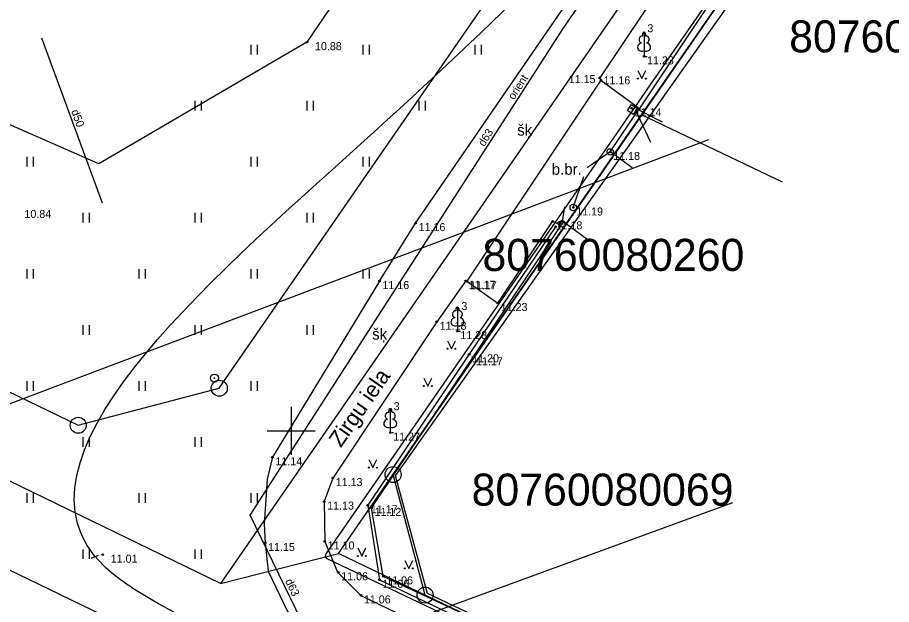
# Model space of a CAD drawing. Extents: x 503353 to 504004, y 304662 to 305049.
# Drawn here: x 503582.9 to 503637.5, y 304889.2 to 304925.8 of the extents above; entities that cross this region are included whole.
import ezdxf

# ---------------------------------------------------------------- set-up
doc = ezdxf.new("R2010")
doc.units = 0
for name, color, linetype in [('13', 7, 'Continuous'), ('24', 7, 'Continuous'), ('25', 7, 'Continuous'), ('59', 7, 'Continuous'), ('APGR_ELEM_####_####_#', 7, 'Continuous'), ('APGR_SARK_####_####_#', 7, 'Continuous'), ('BUVE_ELEM_####_####_#', 7, 'Continuous'), ('CELI_CAPM_####_####_#', 7, 'Continuous'), ('CELI_CMAL_####_####_#', 7, 'Continuous'), ('CELI_CSEG_####_TKST_#', 7, 'Continuous'), ('CELI_IELA_####_TKST_#', 7, 'Continuous'), ('DREN_VADP_####_####_#', 7, 'Continuous'), ('DREN_VADP_####_TKST_#', 7, 'Continuous'), ('ELEK_ELEM_####_####_#', 7, 'Continuous'), ('ELEK_VADP_ZSPR_####_#', 7, 'Continuous'), ('ELEK_VADP_ZSPR_####_I', 7, 'Continuous'), ('GEOD_ELEM_####_####_#', 7, 'Continuous'), ('NORB_ELEM_####_####_#', 7, 'Continuous'), ('NORB_ZOGS_BARJ_####_#', 7, 'Continuous'), ('NORB_ZOGS_KBST_####_#', 7, 'Continuous'), ('NORB_ZOGS_ZSTP_####_#', 7, 'Continuous'), ('RAMI_UZMR_####_####_#', 7, 'Continuous'), ('RELJ_AATZ_####_TKST_#', 7, 'Continuous'), ('RELJ_ELEM_####_####_#', 7, 'Continuous'), ('RELJ_HORZ_PAMT_####_#', 7, 'Continuous'), ('TERT_DIAM_####_TKST_#', 7, 'Continuous'), ('TERT_ELEM_####_####_#', 7, 'Continuous'), ('TERT_KRND_####_####_#', 7, 'Continuous'), ('UDTK_VADP_UDEN_####_#', 7, 'Continuous'), ('UDTK_VADP_UDEN_TKST_#', 7, 'Continuous')]:
    doc.layers.add(name, color=color, linetype=linetype)

msp = doc.modelspace()

# ---------------------------------------------------------------- linework, layer by layer
at = {"layer": '13'}
msp.add_line((503595.592, 304890.48), (503602.955, 304892.334), dxfattribs=at)
at = {"layer": '24'}
for p, q in [((503427.051, 304966.576), (503597.271, 304884.111)), ((503621.894, 304919.725), (503640.119, 304946.083)), ((503602.955, 304892.334), (503621.894, 304919.725)), ((503630.694, 304915.516), (503621.894, 304919.725)), ((503624.198, 304882.173), (503602.955, 304892.334))]:
    msp.add_line(p, q, dxfattribs=at)
at = {"layer": '25'}
for p, q in [((503672.032, 305001.026), (503595.592, 304890.48)), ((503595.592, 304890.48), (503425.185, 304973.036))]:
    msp.add_line(p, q, dxfattribs=at)
at = {"layer": 'APGR_ELEM_####_####_#'}
for p, q in [((503412.342, 304984.814), (503586.697, 304900.345)), ((503586.697, 304900.345), (503595.509, 304902.665))]:
    msp.add_line(p, q, dxfattribs=at)
for centre in [(503595.51, 304902.66), (503586.697, 304900.345), (503606.37, 304897.27), (503608.37, 304889.75)]:
    msp.add_circle(centre, 0.5, dxfattribs=at)
at = {"layer": 'APGR_SARK_####_####_#'}
for p, q in [((503595.509, 304902.665), (503658.316, 304993.498)), ((503669.455, 304988.508), (503606.367, 304897.269)), ((503608.368, 304889.745), (503606.367, 304897.269)), ((503608.368, 304889.745), (503663.371, 304863.436))]:
    msp.add_line(p, q, dxfattribs=at)
at = {"layer": 'BUVE_ELEM_####_####_#'}
for radius in [0.25, 0.0225]:
    msp.add_circle((503595.201, 304903.293), radius, dxfattribs=at)
at = {"layer": 'CELI_CAPM_####_####_#'}
for points in [[(503630.569, 304938.881), (503619.284, 304922.036)], [(503610.905, 304909.365), (503609.095, 304906.808)], [(503609.095, 304906.808), (503602.599, 304897.052), (503602.064, 304895.584), (503602.097, 304893.098), (503602.892, 304891.173), (503604.357, 304889.726), (503615.235, 304884.473)]]:
    msp.add_lwpolyline(points, dxfattribs=at)
at = {"layer": 'CELI_CMAL_####_####_#'}
msp.add_line((503616.895, 304913.13), (503616.726, 304912.877), dxfattribs=at)
for points in [[(503605.515, 304909.352), (503607.775, 304912.97), (503627.397, 304941.5), (503635.622, 304953.341), (503652.6, 304978.844), (503660.954, 304992.392), (503665.471, 305000.768), (503665.873, 305004.349)], [(503619.355, 304921.886), (503610.984, 304909.339)], [(503619.355, 304921.886), (503619.284, 304922.036)], [(503619.355, 304921.886), (503621.767, 304920.122)], [(503619.956, 304917.442), (503621.303, 304916.444)], [(503610.984, 304909.339), (503612.908, 304907.978), (503616.334, 304913.075)], [(503616.726, 304912.877), (503616.334, 304913.075)], [(503618.566, 304911.899), (503616.895, 304913.13)], [(503605.515, 304909.352), (503598.832, 304898.348), (503598.495, 304896.981), (503598.304, 304894.181), (503598.372, 304892.998), (503598.556, 304891.243), (503599.775, 304888.73), (503600.779, 304887.549), (503613.299, 304880.595)], [(503610.984, 304909.339), (503610.905, 304909.365)]]:
    msp.add_lwpolyline(points, dxfattribs=at)
at = {"layer": 'DREN_VADP_####_####_#'}
for p, q in [((503584.392, 304924.543), (503588.201, 304914.224)), ((503626.085, 304918.174), (503556.295, 304891.838)), ((503582.914, 304879.217), (503627.601, 304895.534))]:
    msp.add_line(p, q, dxfattribs=at)
at = {"layer": 'ELEK_ELEM_####_####_#'}
msp.add_lwpolyline([(503621.008, 304919.992), (503621.254, 304920.366), (503621.622, 304920.124), (503621.376, 304919.75)], close=True, dxfattribs=at)
at = {"layer": 'ELEK_VADP_ZSPR_####_#'}
for points in [[(503657.3, 304972.484), (503638.321, 304944.533), (503622.227, 304921.298)], [(503621.488, 304920.052), (503622.446, 304918.016)]]:
    msp.add_lwpolyline(points, dxfattribs=at)
at = {"layer": 'ELEK_VADP_ZSPR_####_I'}
for points in [[(503622.292, 304921.392), (503602.156, 304892.321), (503602.127, 304892.156), (503602.234, 304892.027)], [(503602.234, 304892.027), (503656.944, 304865.995), (503664.699, 304862.319)]]:
    msp.add_lwpolyline(points, dxfattribs=at)
at = {"layer": 'GEOD_ELEM_####_####_#'}
for p, q in [((503600, 304901.5), (503600, 304900)), ((503600, 304901.5), (503600, 304900)), ((503598.5, 304900), (503600, 304900)), ((503598.5, 304900), (503600, 304900)), ((503600, 304900), (503600, 304898.5)), ((503600, 304900), (503601.5, 304900)), ((503600, 304900), (503600, 304898.5)), ((503600, 304900), (503601.5, 304900))]:
    msp.add_line(p, q, dxfattribs=at)
at = {"layer": 'NORB_ELEM_####_####_#'}
for centre in [(503619.935, 304917.41), (503617.625, 304913.944), (503616.923, 304912.922)]:
    msp.add_circle(centre, 0.202, dxfattribs=at)
at = {"layer": 'NORB_ZOGS_BARJ_####_#'}
for p, q in [((503619.935, 304917.41), (503618.493, 304916.425)), ((503617.625, 304913.944), (503618.287, 304915.868)), ((503616.923, 304912.922), (503617.09, 304913.981))]:
    msp.add_line(p, q, dxfattribs=at)
at = {"layer": 'NORB_ZOGS_KBST_####_#'}
for points in [[(503635.703, 304941.016), (503621.748, 304920.094)], [(503619.935, 304917.41), (503621.748, 304920.094)], [(503611.363, 304904.598), (503616.923, 304912.922)], [(503614.907, 304886.637), (503605.755, 304890.915), (503605.024, 304895.191), (503611.363, 304904.598)]]:
    msp.add_lwpolyline(points, dxfattribs=at)
at = {"layer": 'NORB_ZOGS_ZSTP_####_#'}
msp.add_lwpolyline([(503621.734, 304920.015), (503623.173, 304919.292)], dxfattribs=at)
at = {"layer": 'RAMI_UZMR_####_####_#'}
msp.add_lwpolyline([(503825.923, 304784.828), (503697.433, 304847.709), (503608.51, 304889.842), (503606.524, 304897.202), (503679.244, 304999.942), (503684.897, 305009.76), (503666.777, 305017.939), (503656.134, 304996.39), (503644.103, 304987.6), (503600.987, 304924.263), (503587.985, 304916.668), (503422.237, 304989.372), (503408.615, 305023.495), (503368.776, 305020.183)], dxfattribs=at)
at = {"layer": 'RELJ_ELEM_####_####_#'}
for centre in [(503600.987, 304924.263), (503622.049, 304923.378), (503619.284, 304922.036), (503619.355, 304921.886), (503621.278, 304920.14), (503621.748, 304920.094), (503619.935, 304917.41), (503617.625, 304913.944), (503607.775, 304912.97), (503616.334, 304913.075), (503616.923, 304912.922), (503616.521, 304912.741), (503616.799, 304912.818), (503605.515, 304909.352), (503610.905, 304909.365), (503610.984, 304909.339), (503612.908, 304907.978), (503609.095, 304906.808), (503610.384, 304906.224), (503611.124, 304904.78), (503611.363, 304904.598), (503606.191, 304899.888), (503598.832, 304898.348), (503602.599, 304897.052), (503602.064, 304895.584), (503604.791, 304895.355), (503605.024, 304895.191), (503598.372, 304892.998), (503602.097, 304893.098), (503588.225, 304892.269), (503602.942, 304891.173), (503605.52, 304890.703), (503605.755, 304890.915), (503604.357, 304889.726)]:
    msp.add_circle(centre, 0.05, dxfattribs=at)
at = {"layer": 'RELJ_HORZ_PAMT_####_#'}
msp.add_line((503587.496, 304892.056), (503587.957, 304892.249), dxfattribs=at)
msp.add_spline([(503653.856, 304861.224), (503644.002, 304865.053), (503628.506, 304872.58), (503611.965, 304878.986), (503602.441, 304884.188), (503591.366, 304889.404), (503588.291, 304891.572), (503604.352, 304917.909), (503624.778, 304937.692)], degree=3, dxfattribs=at)
at = {"layer": 'TERT_ELEM_####_####_#'}
for p, q in [((503597.5, 304923.5), (503597.5, 304924.1)), ((503597.9, 304923.5), (503597.9, 304924.1)), ((503604.5, 304923.5), (503604.5, 304924.1)), ((503604.9, 304923.5), (503604.9, 304924.1)), ((503611.5, 304923.5), (503611.5, 304924.1)), ((503611.9, 304923.5), (503611.9, 304924.1)), ((503622.049, 304923.725), (503622.049, 304923.378)), ((503622.049, 304923.378), (503622.249, 304923.378)), ((503621.668, 304922.488), (503621.918, 304921.988)), ((503621.918, 304921.988), (503622.168, 304922.488)), ((503594, 304920), (503594, 304920.6)), ((503594.4, 304920), (503594.4, 304920.6)), ((503601, 304920), (503601, 304920.6)), ((503601.4, 304920), (503601.4, 304920.6)), ((503608, 304920), (503608, 304920.6)), ((503608.4, 304920), (503608.4, 304920.6)), ((503583.5, 304916.5), (503583.5, 304917.1)), ((503583.9, 304916.5), (503583.9, 304917.1)), ((503597.5, 304916.5), (503597.5, 304917.1)), ((503597.9, 304916.5), (503597.9, 304917.1)), ((503604.5, 304916.5), (503604.5, 304917.1)), ((503604.9, 304916.5), (503604.9, 304917.1)), ((503587, 304913), (503587, 304913.6)), ((503587.4, 304913), (503587.4, 304913.6)), ((503594, 304913), (503594, 304913.6)), ((503594.4, 304913), (503594.4, 304913.6)), ((503601, 304913), (503601, 304913.6)), ((503601.4, 304913), (503601.4, 304913.6)), ((503583.5, 304909.5), (503583.5, 304910.1)), ((503583.9, 304909.5), (503583.9, 304910.1)), ((503590.5, 304909.5), (503590.5, 304910.1)), ((503590.9, 304909.5), (503590.9, 304910.1)), ((503597.5, 304909.5), (503597.5, 304910.1)), ((503597.9, 304909.5), (503597.9, 304910.1)), ((503604.5, 304909.5), (503604.5, 304910.1)), ((503604.9, 304909.5), (503604.9, 304910.1)), ((503587, 304906), (503587, 304906.6)), ((503587.4, 304906), (503587.4, 304906.6)), ((503594, 304906), (503594, 304906.6)), ((503594.4, 304906), (503594.4, 304906.6)), ((503601, 304906), (503601, 304906.6)), ((503601.4, 304906), (503601.4, 304906.6)), ((503610.384, 304906.571), (503610.384, 304906.224)), ((503610.384, 304906.224), (503610.584, 304906.224)), ((503609.759, 304905.626), (503610.009, 304905.126)), ((503610.009, 304905.126), (503610.259, 304905.626)), ((503583.5, 304902.5), (503583.5, 304903.1)), ((503583.9, 304902.5), (503583.9, 304903.1)), ((503590.5, 304902.5), (503590.5, 304903.1)), ((503590.9, 304902.5), (503590.9, 304903.1)), ((503597.5, 304902.5), (503597.5, 304903.1)), ((503597.9, 304902.5), (503597.9, 304903.1)), ((503608.286, 304903.295), (503608.536, 304902.795)), ((503608.536, 304902.795), (503608.786, 304903.295)), ((503606.191, 304900.235), (503606.191, 304899.888)), ((503606.191, 304899.888), (503606.391, 304899.888)), ((503587, 304899), (503587, 304899.6)), ((503587.4, 304899), (503587.4, 304899.6)), ((503594, 304899), (503594, 304899.6)), ((503594.4, 304899), (503594.4, 304899.6)), ((503604.846, 304898.204), (503605.096, 304897.704)), ((503605.096, 304897.704), (503605.346, 304898.204)), ((503583.5, 304895.5), (503583.5, 304896.1)), ((503583.9, 304895.5), (503583.9, 304896.1)), ((503590.5, 304895.5), (503590.5, 304896.1)), ((503590.9, 304895.5), (503590.9, 304896.1)), ((503597.5, 304895.5), (503597.5, 304896.1)), ((503597.9, 304895.5), (503597.9, 304896.1)), ((503604.166, 304892.687), (503604.416, 304892.187)), ((503604.416, 304892.187), (503604.666, 304892.687)), ((503587, 304892), (503587, 304892.6)), ((503587.4, 304892), (503587.4, 304892.6)), ((503594, 304892), (503594, 304892.6)), ((503594.4, 304892), (503594.4, 304892.6)), ((503607.107, 304891.913), (503607.357, 304891.413)), ((503607.357, 304891.413), (503607.607, 304891.913))]:
    msp.add_line(p, q, dxfattribs=at)
for points in [[(503622.049, 304924.878), (503622.049, 304923.725)], [(503622.139, 304924.646), (503622.138, 304924.647)], [(503610.384, 304907.724), (503610.384, 304906.571)], [(503610.474, 304907.492), (503610.473, 304907.493)], [(503606.191, 304901.388), (503606.191, 304900.235)], [(503606.281, 304901.156), (503606.28, 304901.157)]]:
    msp.add_lwpolyline(points, dxfattribs=at)
for centre, radius in [((503621.667, 304921.988), 0.028), ((503622.167, 304921.988), 0.0263), ((503609.758, 304905.126), 0.028), ((503610.258, 304905.126), 0.0263), ((503608.286, 304902.794), 0.028), ((503608.786, 304902.794), 0.0263), ((503604.846, 304897.703), 0.028), ((503605.346, 304897.703), 0.0263), ((503604.165, 304892.186), 0.028), ((503604.665, 304892.186), 0.0263), ((503607.107, 304891.413), 0.028), ((503607.607, 304891.413), 0.0263)]:
    msp.add_circle(centre, radius, dxfattribs=at)
for centre, major_axis, ratio, start_param, end_param in [((503621.921, 304924.433), (-0.039, -0.212), 0.861323, 3.141593, 6.283185), ((503622.049, 304924.728), (0, -0.15), 0.707107, 3.14537, 5.287485), ((503622.049, 304924.728), (0, -0.15), 0.707107, 0.995701, 3.137816), ((503622.177, 304924.433), (0.039, -0.212), 0.861323, 0, 3.141593), ((503621.959, 304923.971), (0.307, 0.095), 0.814445, 1.570796, 4.752015), ((503622.139, 304923.971), (-0.307, 0.095), 0.814445, 1.531171, 4.712389), ((503610.256, 304907.279), (-0.039, -0.212), 0.861323, 3.141593, 6.283185), ((503610.384, 304907.574), (0, -0.15), 0.707107, 3.14537, 5.287485), ((503610.384, 304907.574), (0, -0.15), 0.707107, 0.995701, 3.137816), ((503610.512, 304907.279), (0.039, -0.212), 0.861323, 0, 3.141593), ((503610.294, 304906.817), (0.307, 0.095), 0.814445, 1.570796, 4.752015), ((503610.474, 304906.817), (-0.307, 0.095), 0.814445, 1.531171, 4.712389), ((503606.063, 304900.943), (-0.039, -0.212), 0.861323, 3.141593, 6.283185), ((503606.191, 304901.238), (0, -0.15), 0.707107, 3.14537, 5.287485), ((503606.191, 304901.238), (0, -0.15), 0.707107, 0.995701, 3.137816), ((503606.319, 304900.943), (0.039, -0.212), 0.861323, 0, 3.141593), ((503606.101, 304900.481), (0.307, 0.095), 0.814445, 1.570796, 4.752015), ((503606.281, 304900.481), (-0.307, 0.095), 0.814445, 1.531171, 4.712389)]:
    msp.add_ellipse(centre, major_axis=major_axis, ratio=ratio, start_param=start_param, end_param=end_param, dxfattribs=at)
at = {"layer": 'TERT_KRND_####_####_#'}
msp.add_lwpolyline([(503616.521, 304912.741), (503611.124, 304904.78), (503604.791, 304895.355), (503605.52, 304890.703), (503614.884, 304886.236)], dxfattribs=at)
at = {"layer": 'UDTK_VADP_UDEN_####_#'}
for points in [[(503597.433, 304894.737), (503617.042, 304925.181), (503648.243, 304970.376)], [(503600.655, 304888.132), (503597.433, 304894.737)]]:
    msp.add_lwpolyline(points, dxfattribs=at)

# ---------------------------------------------------------------- texts
at = {"layer": '59'}
for s, p in [('80760080414', (503631.115, 304923.624)), ('80760080260', (503611.952, 304909.985)), ('80760080069', (503611.275, 304895.331))]:
    msp.add_text(s, height=2, dxfattribs=at).set_placement(p)
at = {"layer": 'CELI_CSEG_####_TKST_#'}
for s, p in [('šķ', (503614.123, 304918.428)), ('b.br.', (503616.28, 304915.985)), ('šķ', (503605.06, 304905.693))]:
    msp.add_text(s, height=0.7, dxfattribs=at).set_placement(p)
at = {"layer": 'CELI_IELA_####_TKST_#'}
msp.add_text('Zirgu iela', height=1, rotation=55.2154, dxfattribs=at).set_placement((503603.102, 304898.912))
at = {"layer": 'DREN_VADP_####_TKST_#'}
msp.add_text('d50', height=0.5, rotation=290.263, dxfattribs=at).set_placement((503586.246, 304919.953))
at = {"layer": 'RELJ_AATZ_####_TKST_#'}
for s, p in [('10.88', (503601.487, 304923.763)), (' 11.23', (503622.049, 304922.878)), (' 11.15', (503617.154, 304921.707)), (' 11.16', (503619.328, 304921.629)), (' 11.14', (503621.278, 304919.64)), (' 11.18', (503619.935, 304916.91)), ('10.84', (503583.335, 304913.287)), (' 11.19', (503617.625, 304913.444)), (' 11.16', (503607.775, 304912.47)), (' 11.18', (503616.334, 304912.575)), (' 11.16', (503605.515, 304908.852)), (' 11.17', (503610.905, 304908.865)), (' 11.17', (503610.984, 304908.839)), (' 11.23', (503612.908, 304907.478)), (' 11.18', (503609.095, 304906.308)), (' 11.28', (503610.384, 304905.724)), (' 11.20', (503611.124, 304904.28)), (' 11.17', (503611.363, 304904.098)), (' 11.27', (503606.191, 304899.388)), (' 11.14', (503598.832, 304897.848)), (' 11.13', (503602.599, 304896.552)), (' 11.13', (503602.064, 304895.084)), (' 11.17', (503604.791, 304894.855)), (' 11.12', (503605.024, 304894.691)), (' 11.15', (503598.372, 304892.498)), (' 11.10', (503602.097, 304892.598)), ('11.01', (503588.725, 304891.769)), (' 11.06', (503602.942, 304890.673)), (' 11.06', (503605.52, 304890.203)), (' 11.06', (503605.755, 304890.415)), (' 11.06', (503604.357, 304889.226))]:
    msp.add_text(s, height=0.5, dxfattribs=at).set_placement(p)
at = {"layer": 'TERT_DIAM_####_TKST_#'}
for p in [(503622.256, 304924.883), (503610.635, 304907.538), (503606.405, 304901.289)]:
    msp.add_text('3', height=0.5, dxfattribs=at).set_placement(p)
at = {"layer": 'UDTK_VADP_UDEN_TKST_#'}
for s, rotation, p in [('orient', 57.2144, (503613.926, 304920.628)), ('d63', 57.2144, (503612.054, 304917.714)), ('d63', 296.0064, (503599.607, 304890.622))]:
    msp.add_text(s, height=0.5, rotation=rotation, dxfattribs=at).set_placement(p)

doc.saveas('drawing.dxf')
